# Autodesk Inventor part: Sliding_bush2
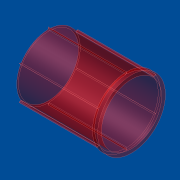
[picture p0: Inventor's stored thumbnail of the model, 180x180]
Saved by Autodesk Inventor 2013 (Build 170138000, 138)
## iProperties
Shininess: 20.0
Length Units: 11269
Angle Units: 11279
Time Units: 11290
Mass Units: 11283
Length Display Precision: 3
Angle Display Precision: 2
Created: 2001-04
Part Number: Sliding_bush2
Material: Standard
Document SubType Name: Modellieren
Designer: dl
Density: 1 g/cm^3
Density: 0.0
Volumn: 0.0
Area: 0.0
PropertySet Name: Model Information
Control State: 0
Master: False
Checked Out: False
Author: dl
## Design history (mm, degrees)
body "Solid1"
revolve "Revolution1" stored, may be unused: angle "d4" = 90 deg
sketch "Sketch2"
  geometry: C1 r 20 at (0, 0) reference; 1 further point
  constraints: 1 coincident
hole "Hole1" sketch "Sketch2" diameter "d5" = 35.5; stored, may be unused: countersink angle "d9" = 60 deg, drill point angle "d11" = 118 deg; dims "d6" = 6, "d7" = 4, "d8" = 2, "d10" = 8
sketch "Sketch3"
  geometry: L1 (0, 20)-(-0.536, 18); L2 (-0.536, 18)-(0.536, 18); L3 (0.536, 18)-(0, 20); C1 r 18.75 at (0, 0) reference
  constraints: 6 end point, 1 horizontal
  dimensions: "d12" = 30 deg angle of L3 L1; "d13" = 75 deg angle of L2 L1; "d14" = 0 horizontal distance of C1.centre L1.start; "d15" = 20 distance of C1.centre L1.start; "d16" = 2 vertical distance of L1.end L1.start
extrude "Extrusion1" join sketch "Sketch3" stored distance "d17" = 10; taper "d18" = 0 deg
pattern_circular "Circular Pattern1" dims angle "d21" = 360 deg
sketch "Sketch1"
  geometry: L1 (18.468, 13.601)-(18.468, 32.351); L2 (18.468, 32.351)-(64.468, 32.351); L3 (64.468, 32.351)-(64.468, 33.601); L4 (64.468, 33.601)-(67.468, 33.601); L5 (67.468, 33.601)-(67.468, 13.601); L6 (67.468, 13.601)-(18.468, 13.601)
  constraints: 12 end point, 3 vertical, 2 perpendicular, 1 horizontal, 1 parallel
  dimensions: "d0" = 20 distance of L4.end L5.end; "d1" = 18.75 distance of L1.start L1.end; "d2" = 3 distance of L3.end L4.end; "d3" = 49 distance of L5.end L1.start
